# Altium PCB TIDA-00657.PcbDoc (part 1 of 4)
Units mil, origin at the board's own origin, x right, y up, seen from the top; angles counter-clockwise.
Board outline 2500 x 2500 mil, 4 copper layers (Top Layer, MidLayer1, MidLayer2, Bottom Layer); 149 components, 57 nets, 332 pads, 124 vias.
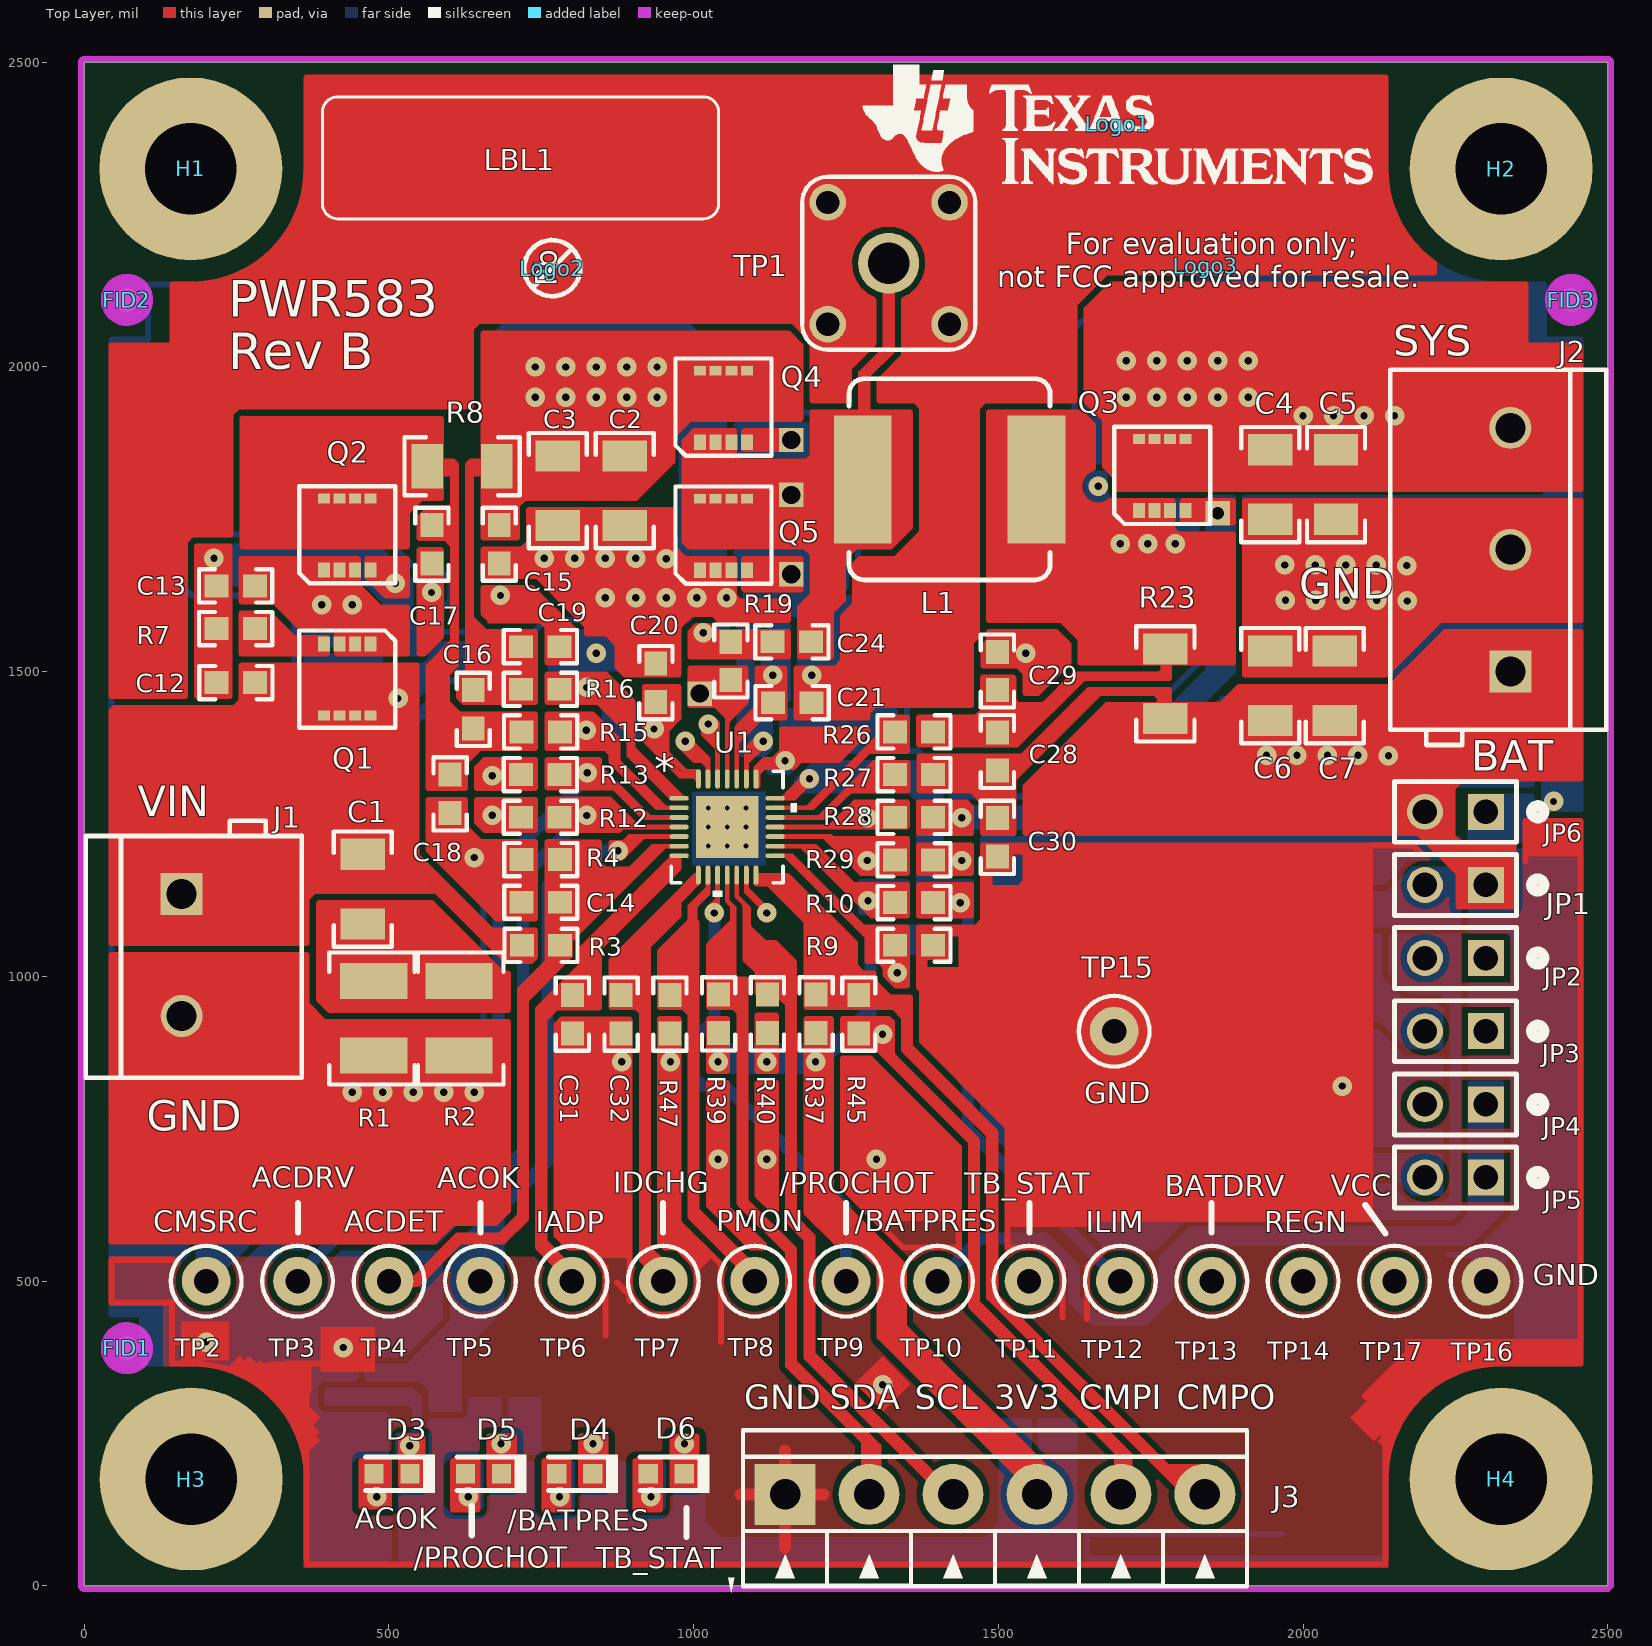
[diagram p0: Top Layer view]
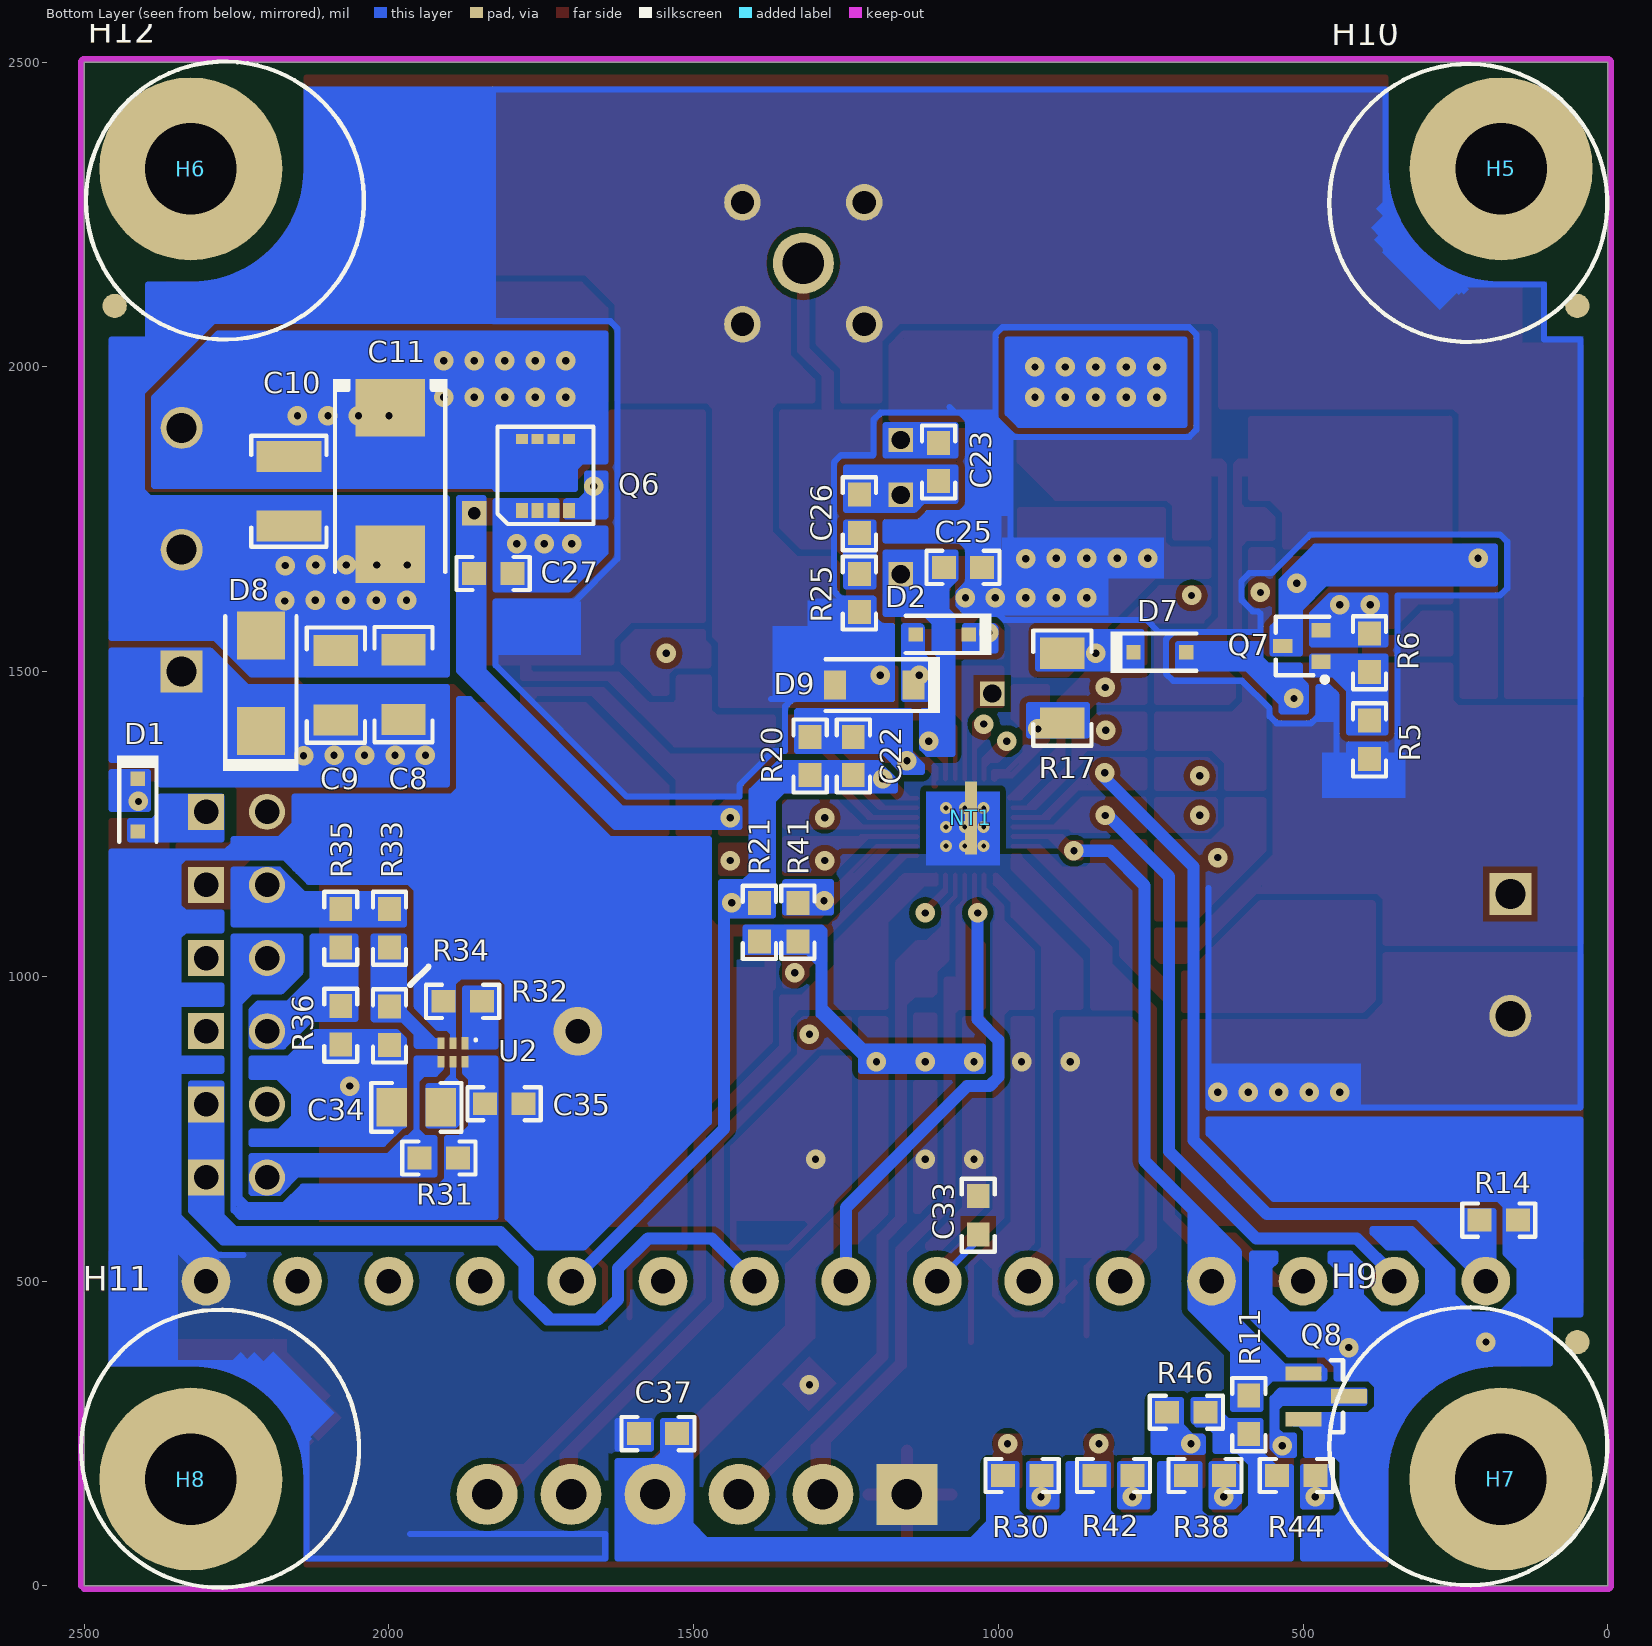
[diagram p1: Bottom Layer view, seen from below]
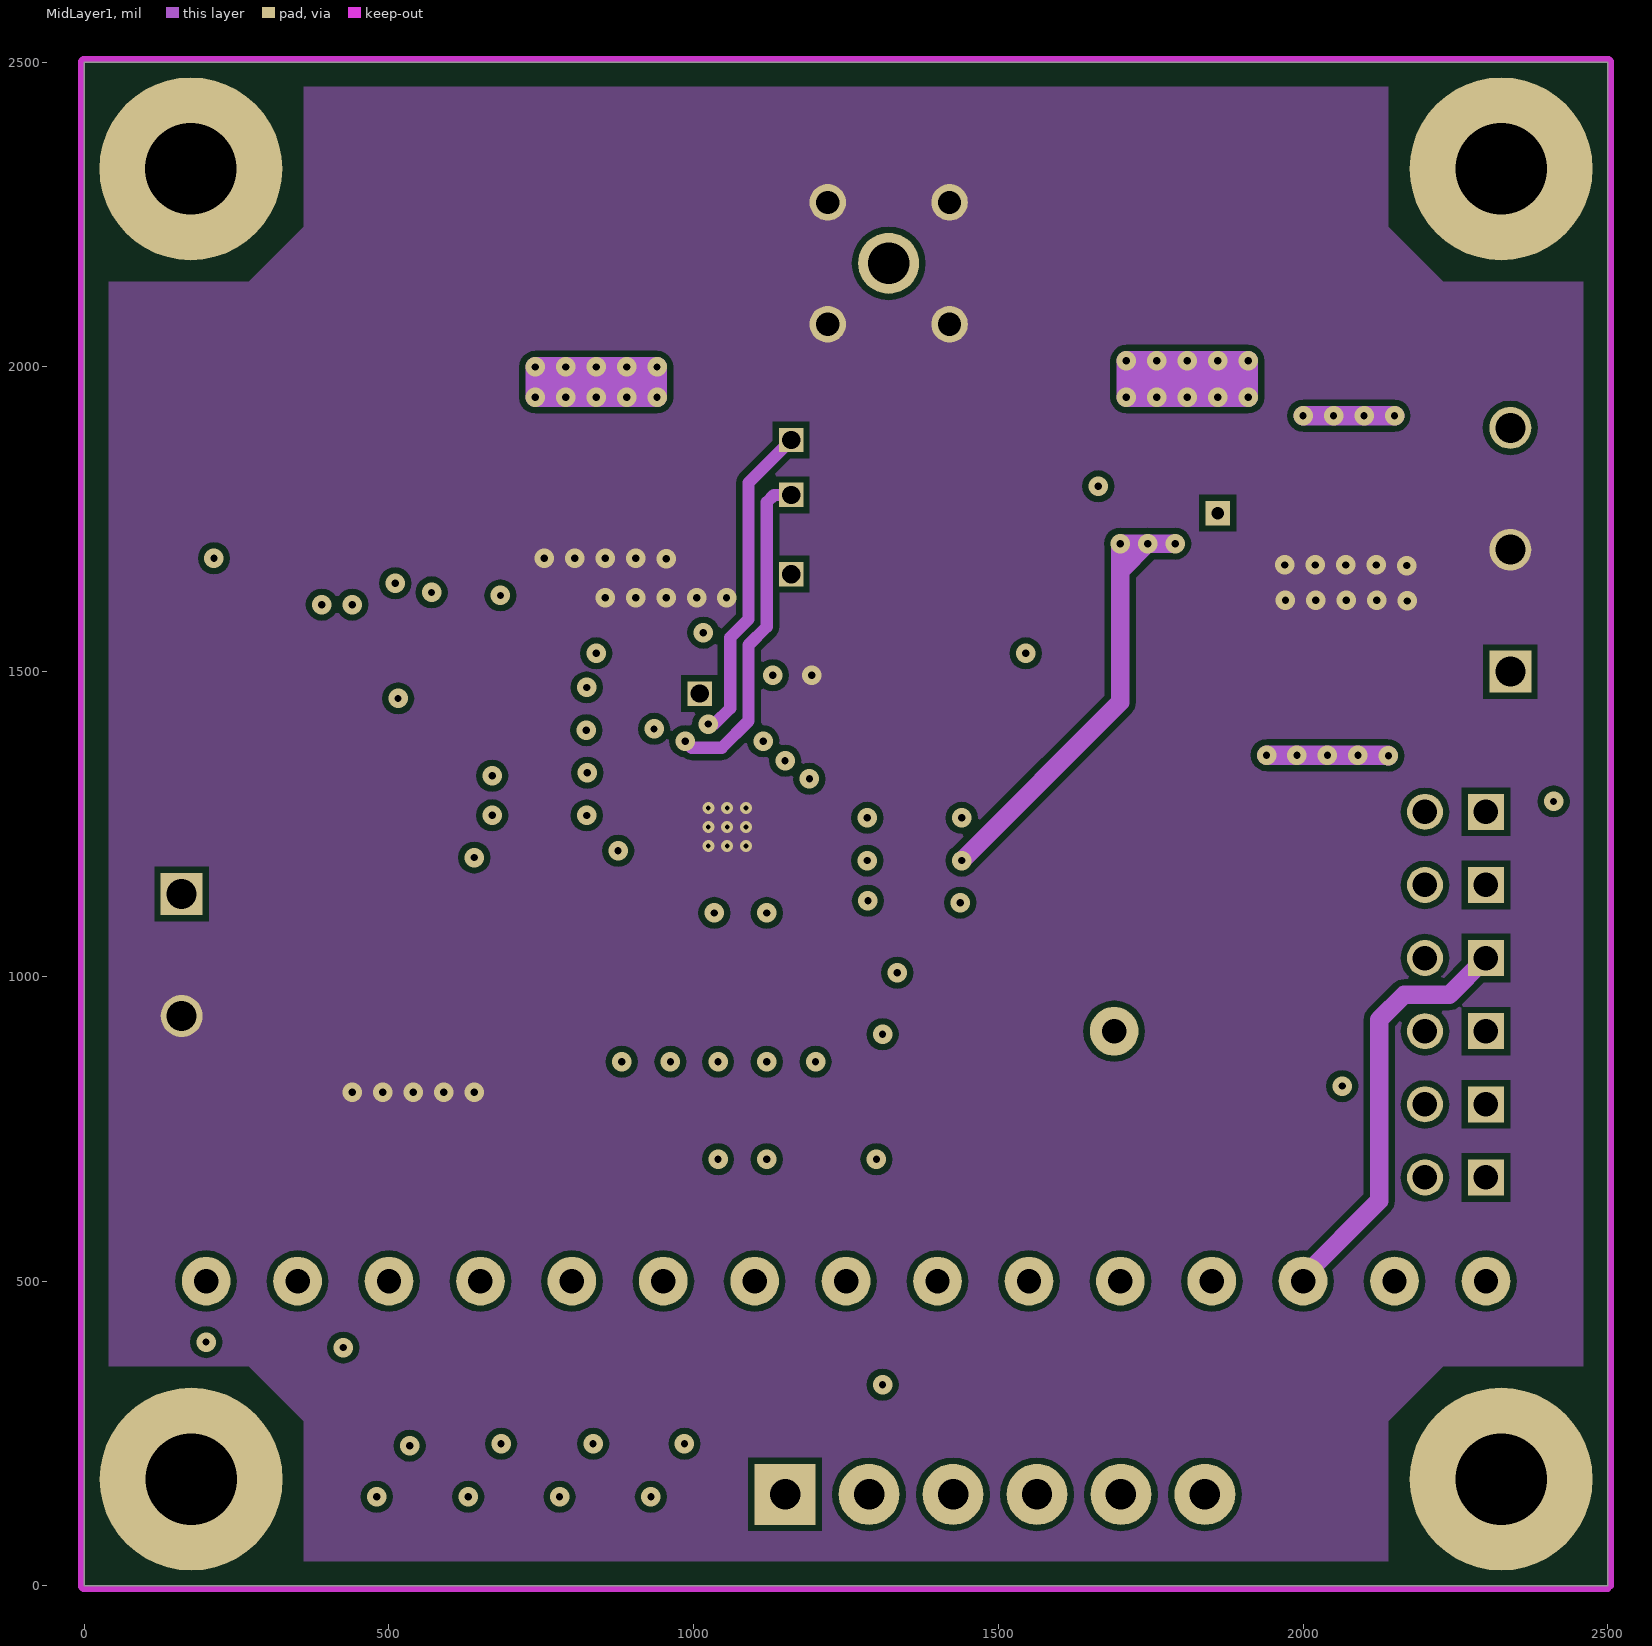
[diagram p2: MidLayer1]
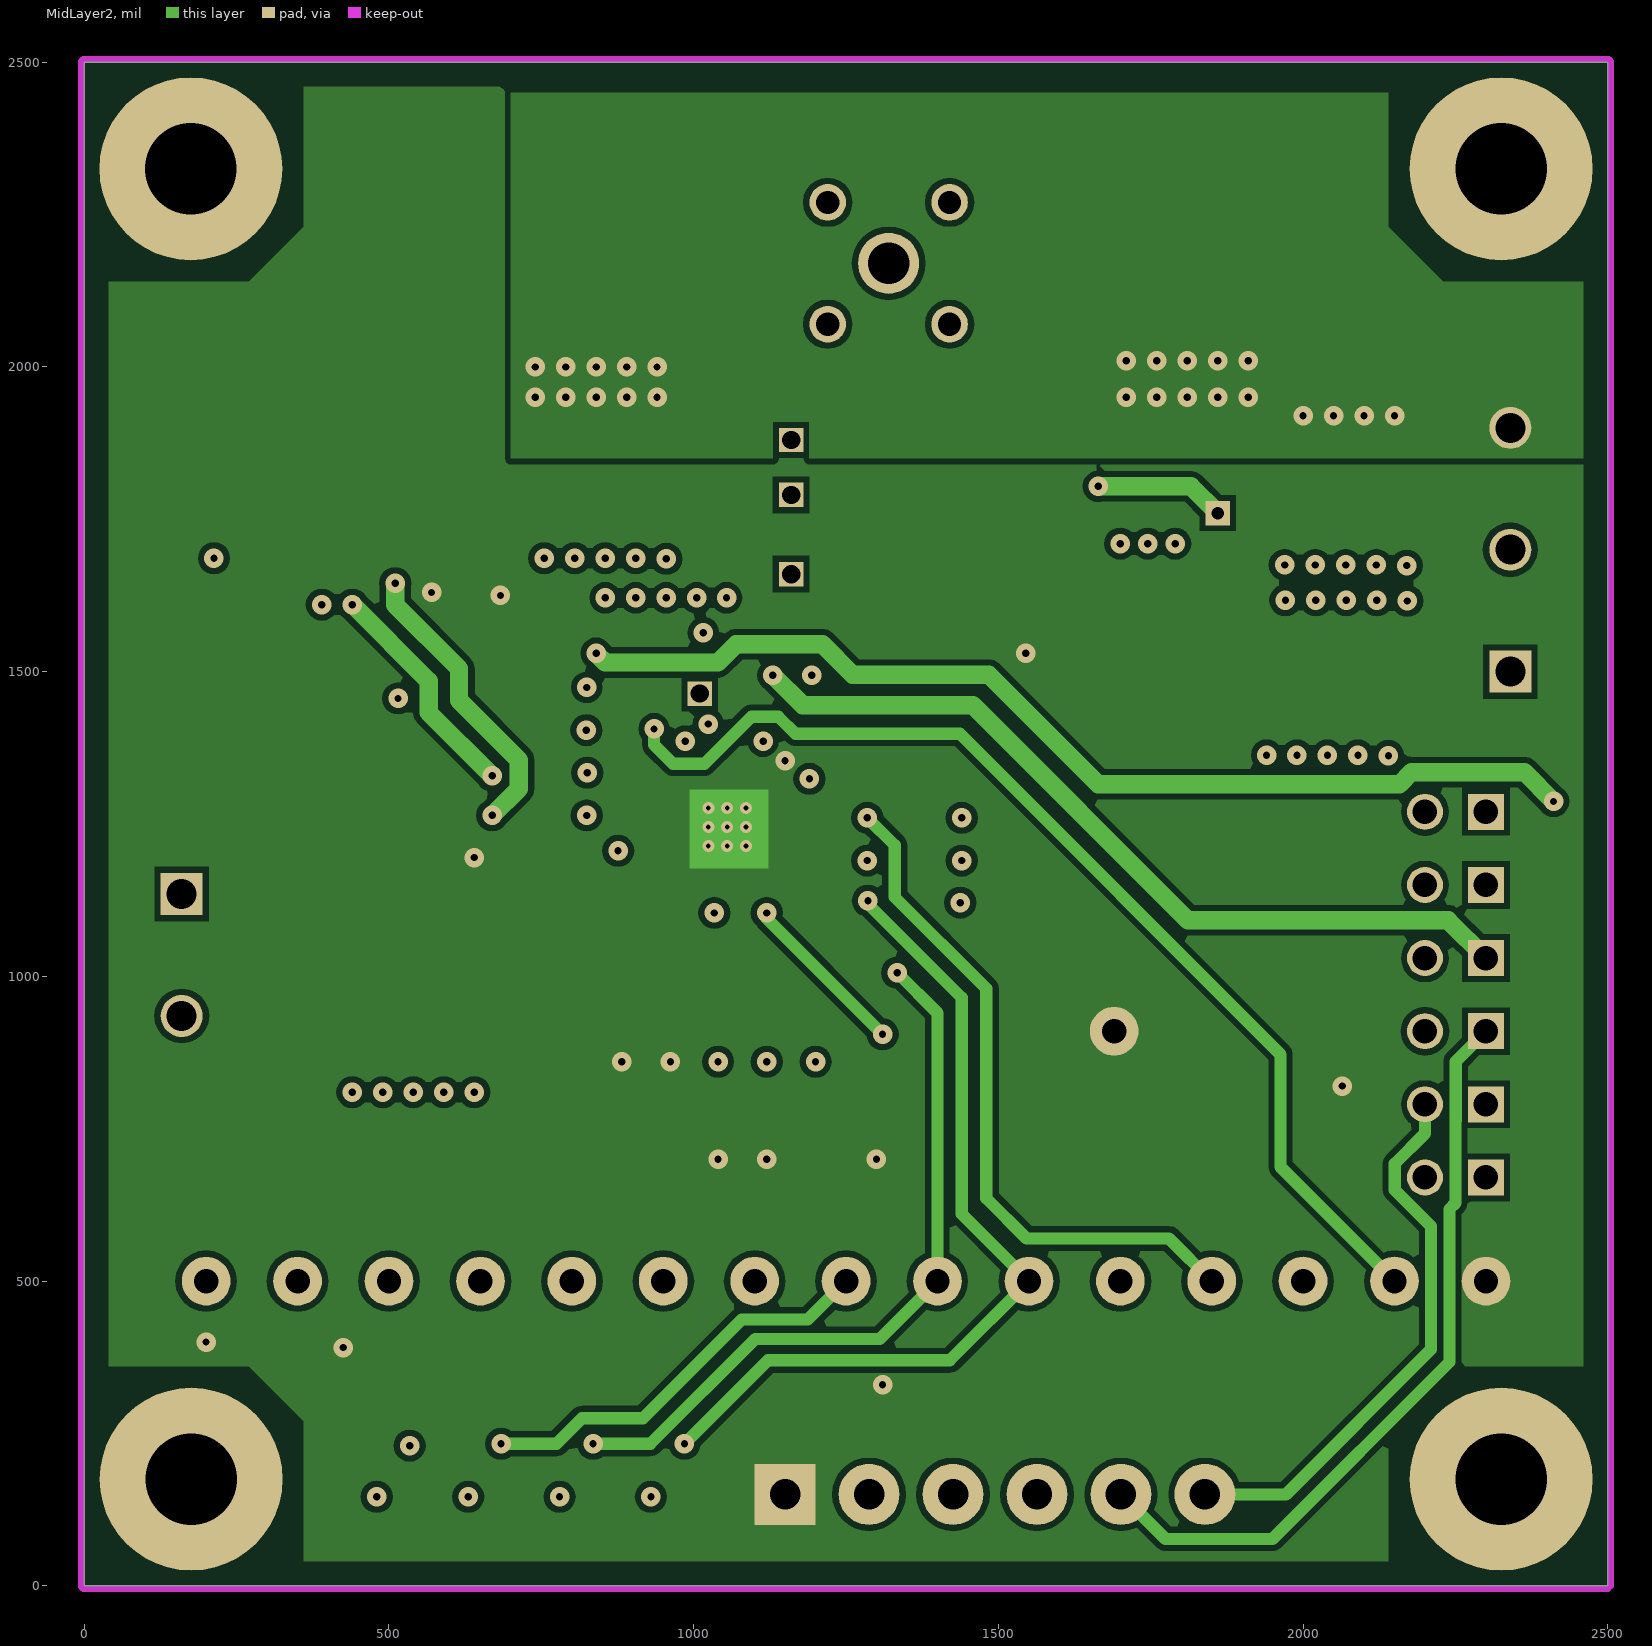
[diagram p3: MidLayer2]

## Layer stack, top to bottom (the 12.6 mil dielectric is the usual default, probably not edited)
Top Solder: solder mask 0.4, Solder Resist, Dk 3.5
Top Layer: signal copper 2.8
Dielectric1: core 12.6, FR-4, Dk 4.8
MidLayer1: signal copper 2.8
Dielectric2: prepreg 12.6, FR-4, Dk 4.8
MidLayer2: signal copper 2.8
Dielectric3: core 12.6, FR-4, Dk 4.8
Bottom Layer: signal copper 2.8
Bottom Solder: solder mask 0.4, Solder Resist, Dk 3.5

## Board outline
0,0 2500,0 2500,2500 0,2500 0,0

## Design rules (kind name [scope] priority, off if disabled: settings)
AcuteAngle [All] p1 off: minimum=4.50000000000000E+0001 checktracksonly=FALSE
AssemblyTestPointUsage [All] p1: valid=2
Clearance Clearance_BoardEdge_MountingHoles [OnCopper and InComponentClass('Mounting Holes') vs IsKeepOut] p1: gap=20
Clearance Clearance_BoardEdge_Poly [OnCopper and InPoly vs IsKeepOut] p2: gap=10
Clearance Clearance_BoardEdge [OnCopper and Not InComponentClass('Logo') and not InComponentClass('FiducialMark') and not InRegion(1000,500,4000,800) and Not IsKeepout vs IsKeepOut] p3: gap=20
Clearance Clearance_Poly [InPolygon] p4: gap=10
Clearance [All] p5: gap=6
ComponentClearance ComponentClearance_Logo [InComponentClass(Logo)] p1: gap=0 collisioncheckmode=3 verticalgap=0 showdistances=FALSE
ComponentClearance ComponentClearance_ScrewToNut [(HasFootprint('NY PMS 440 0025 PH')) vs (HasFootprint('Keystone_1902C'))] p2: gap=0 collisioncheckmode=3 verticalgap=0 showdistances=FALSE
ComponentClearance ComponentClearance_MountingHoles [InComponentClass('Mounting Holes')] p3: gap=0 collisioncheckmode=3 verticalgap=100000 showdistances=FALSE
ComponentClearance ComponentClearance_SmallPassives [HasFootprint('0201*') or HasFootprint('0402*') or HasFootprint('0508') or HasFootprint('0603*') or HasFootprint('0612') or HasFootprint('0805*') or HasFootprint('0815*') or HasFootprint('0830*') or HasFootprint('1206*') or HasFootprint('1210*') or HasFootprint('1808*') or HasFootprint('1812*') or HasFootprint('1825*') or HasFootprint('2010*') or HasFootprint('2220*') or HasFootprint('2225*') or HasFootprint('2512*') or HasFootprint('2728*') or HasFootprint('3518*') vs HasFootprint('0201*') or HasFootprint('0402*') or HasFootprint('0508') or HasFootprint('0603*') or HasFootprint('0612') or HasFootprint('0805*') or HasFootprint('0815*') or HasFootprint('0830*') or HasFootprint('1206*') or HasFootprint('1210*') or HasFootprint('1808*') or HasFootprint('1812*') or HasFootprint('1825*') or HasFootprint('2010*') or HasFootprint('2220*') or HasFootprint('2225*') or HasFootprint('2512*') or HasFootprint('2728*') or HasFootprint('3518*')] p4: gap=0 collisioncheckmode=3 verticalgap=0 showdistances=FALSE
ComponentClearance ComponentClearance_THtoSMT [IsThruComponent vs IsSMTComponent] p5: gap=0 collisioncheckmode=3 verticalgap=0 showdistances=FALSE
ComponentClearance ComponentClearance_THtoTH [IsThruComponent vs IsThruComponent] p6: gap=0 collisioncheckmode=3 verticalgap=0 showdistances=FALSE
ComponentClearance [All] p7: gap=0 collisioncheckmode=3 verticalgap=0 showdistances=FALSE
DiffPairsRouting [All] p1: maxlimit=100 minlimit=10 mostfreqgap=10 toplayer_minwidth=15 toplayer_maxwidth=15 toplayer_prefwidth=15 midlayer1_minwidth=15 midlayer1_maxwidth=15 midlayer1_prefwidth=15 midlayer2_minwidth=15 midlayer2_maxwidth=15 midlayer2_prefwidth=15 bottomlayer_minwidth=15 bottomlayer_maxwidth=15 bottomlayer_prefwidth=15 maxuncoupledlength=1000
FabricationTestPointUsage TestPointUsage [All] p1: valid=2 allowmultiple=FALSE
FabricationTestpoint Testpoint [All] p1: side=3 testpointundercomponent=TRUE minsize=40 maxsize=100 preferedsize=60 minholesize=0 maxholesize=40 preferedholesize=32 testpointgrid=1 allowsidetop=TRUE allowsidebottom=TRUE usegrid=TRUE gridtolerance=0.01
FanoutControl Fanout_LCC [IsLCC] p1: bgadir=Out bgaviamode=Centered fanoutstyle=Auto fanoutdirection=Alternating viagrid=1 // Fanout_LCC (Default Rule)
FanoutControl Fanout_BGA [IsBGA] p2: bgadir=Out bgaviamode=Centered fanoutstyle=Auto fanoutdirection=Alternating viagrid=1 // Fanout_BGA (Default Rule)
FanoutControl Fanout_Default [All] p4: bgadir=Out bgaviamode=Centered fanoutstyle=Auto fanoutdirection=Alternating viagrid=1 // Fanout_Default (Default Rule)
FanoutControl Fanout_Small [(CompPinCount < 5)] p5: bgadir=Out bgaviamode=Centered fanoutstyle=Auto fanoutdirection=OutThenIn viagrid=1 // Fanout_Small (Default Rule)
HoleSize [All] p1: absolutevalues=TRUE maxlimit=251 minlimit=6 maxpercent=80.000 minpercent=20.000
MinimumAnnularRing [All] p1: minimumring=5
MinimumSolderMaskSliver MinimumSolderMaskSliver_Logo [InComponentClass('Logo') vs InComponentClass('Logo')] p1: minsoldermaskwidth=0.7
MinimumSolderMaskSliver [All] p2: minsoldermaskwidth=4
PlaneClearance [All] p1: clearance=10
PlaneConnect [All] p1: planeconnectstyle=Direct reliefexpansion=10 reliefentries=4 reliefconductorwidth=10 reliefairgap=10
PolygonConnect [All] p1: connectstyle=Direct reliefconductorwidth=10 reliefentries=4 polygonreliefangle="90 Angle" airgapwidth=10
RoutingVias [All] p1: holewidth=16 width=34 viastyle="Through Hole" minholewidth=5 minwidth=18 maxholewidth=200 maxwidth=400
SMDToCorner [All] p1: distance=0
ShortCircuit [All] p1: allowed=TRUE
SilkToBoardRegionClearance [All] p1 off:
SilkToSilkClearance [All] p1: silktosilkclearance=0
SilkToSolderMaskClearance SilkscreenOverComponentPads [IsPad] p1: minsilkscreentomaskgap=0 clearancetoexposedcopper=TRUE
SolderMaskExpansion [All] p1: expansion=0
UnpouredPolygon [All] p1: allowunpoured=FALSE
Width [All] p1: maxlimit=100 minlimit=6 preferedwidth=10 checkconnectedcopper=TRUE
12 further rules are at their usual default settings.

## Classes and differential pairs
component class AssemblyNote: ZZ1 ZZ2 ZZ3 ZZ4
component class Label: LBL1
component class FiducialMark: FID1 FID2 FID3
component class "PWR583RevB Hardware_ANSI-B": FID1 FID2 FID3 H1 H2 H3 H4 H5 H6 H7 H8 H9 H10 H11 H12 LBL1 Logo1 Logo2 Logo3 ZZ1 ZZ2 ZZ3 ZZ4
component class Logo: Logo1
component class "Mounting Holes": H1 H2 H3 H4
component class PWR583RevB: C1 C2 C3 C4 C5 C6 C7 C8 C9 C10 C11 C12 C13 C14 C15 C16 C17 C18 C19 C20 C21 C22 C23 C24 C25 C26 C27 C28 C29 C30 C31 C32 C33 C34 C35 C37 D1 D2 D3 D4 D5 D6 D7 D8 D9 J1 J2 J3 JP1 JP2 JP3 JP4 JP5 JP6 L1 NT1 Q1 Q2 Q3 Q4 Q5 Q6 Q7 Q8 R1 R2 R3 R4 R5 R6 R7 R8 R9 R10 R11 R12 R13 R14 R15 R16 R17 R19 R20 R21 R23 R25 R26 R27 R28 R29 R30 R31 R32 R33 R34 R35 R36 R37 R38 R39 R40 R41 R42 R44 R45 R46 R47 TP1 TP2 TP3 TP4 TP5 TP6 TP7 TP8 TP9 TP10 TP11 TP12 TP13 TP14 TP15 TP16 TP17 U1 U2

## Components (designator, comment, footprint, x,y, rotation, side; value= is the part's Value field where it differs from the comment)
C1 "GRM31MR71E225KA93L" 1206 457,1143.24 r270 top
C2 "GRM31CR61E106KA12L" 1206 887,1796.91 r270 top
C3 "GRM31CR61E106KA12L" 1206 777,1796.91 r270 top
C4 "GRM31CR61E106KA12L" 1206 1946,1807 r270 top
C5 "GRM31CR61E106KA12L" 1206 2054,1807 r270 top
C6 "GRM31CR61E106KA12L" 1206 1946,1477 r90 top
C7 "GRM31CR61E106KA12L" 1206 2052,1477 r90 top
C8 "GRM31CR61E106KA12L" 1206 1976,1478.76 r90 bottom
C9 "GRM31CR61E106KA12L" 1206 2087,1477.76 r90 bottom
C10 "GRM32ER61E226KE15L" 1210 2164,1795.98 r270 bottom
C11 "16TQC150MYF" 7343-28 1998,1812.98 r270 bottom
C12 "GRM188R71H102KA01D" 0603 249,1482 r180 top
C13 "GRM188R71H473KA61D" 0603 248.54,1640.66 r180 top
C14 "GRM188R71E104KA01D" 0603 749.13,1121.63 r180 top
C15 "GRM188R71E105KA12D" 0603 681,1709 r270 top
C16 "GRM188R71E104KA01D" 0603 638.37,1438.13 r90 top
C17 "GRM188R71E105KA12D" 0603 570.54,1708.99 r270 top
C18 "GRM188R71E104KA01D" 0603 600.37,1299.45 r270 top
C19 "GRM188R71E104KA01D" 0603 748.5,1541 r0 top
C20 "GRM188R71E105KA12D" 0603 938,1482.06 r90 top
C21 "GRM188R61C225KE15D" 0603 1161.5,1449 r0 top
C22 "C0603X103K5RACTU" 0603 1238,1361.5 r270 bottom
C23 "GRM188R71E104KA01D" 0603 1098,1844 r270 bottom
C24 "GRM188R71H473KA61D" 0603 1161.14,1548.87 r0 top
C25 "GRM188R71H471KA01D" 0603 1058,1671 r180 bottom
C26 "GRM188R71E104KA01D" 0603 1228,1759 r270 bottom
C27 "C0603X103K5RACTU" 0603 1829,1661 r180 bottom
C28 "GRM188R71E104KA01D" 0603 1498.5,1369 r270 top
C29 "GRM188R71E104KA01D" 0603 1498.5,1501 r90 top
C30 "GRM188R71E104KA01D" 0603 1498.5,1228 r270 top
C31 "C0603C101J5GAC" 0603 801,938 r270 top
C32 "C0603C101J5GAC" 0603 881,938 r270 top
C33 "C0603C101J5GAC" 0603 1033,608 r90 bottom
C34 "C2012C0G1H222J" 0805_HV 1955,785 r180 bottom
C35 "GRM188R71E104KA01D" 0603 1811,791 r0 bottom
C37 "GRM188R71A225KE15D" 0603 1558.48,249.77 r0 bottom
D1 "BAT54HT1G" sod-323 2412,1281 r270 bottom
D2 "BAT54HT1G" sod-323 1092,1561 r0 bottom
D3 "LTST-C190GKT" LED_LTST-C190 505.06,184 r0 top
D4 "LTST-C190GKT" LED_LTST-C190 805,184 r0 top
D5 "LTST-C190KFKT" LED_LTST-C190 655,184 r0 top
D6 "LTST-C190KFKT" LED_LTST-C190 955,184 r0 top
D7 "BAT54HT1G" sod-323 735,1532 r180 bottom
D8 "SS12-E3/61T" SMA 2210,1480.95 r90 bottom
D9 "BZT52C8V2-7-F" SOD-123 1203.5,1478 r0 bottom
FID1 "Fiducial" Fiducial10-20 70,390 r0 top
FID2 "Fiducial" Fiducial10-20 70,2110 r0 top
FID3 "Fiducial" Fiducial10-20 2440,2110 r0 top
H1 "NY PMS 440 0025 PH" "NY PMS 440 0025 PH" 175,2325 r0 top locked
H2 "NY PMS 440 0025 PH" "NY PMS 440 0025 PH" 2325,2325 r0 top locked
H3 "NY PMS 440 0025 PH" "NY PMS 440 0025 PH" 175.53,175 r0 top locked
H4 "NY PMS 440 0025 PH" "NY PMS 440 0025 PH" 2325,175 r0 top locked
H5 "1902C" Keystone_1902C 175,2325 r180 bottom locked
H6 "1902C" Keystone_1902C 2325.53,2325 r180 bottom locked
H7 "1902C" Keystone_1902C 175.53,175 r180 bottom locked
H8 "1902C" Keystone_1902C 2325,175 r180 bottom locked
H9 "SJ-5303 (CLEAR)" Bumpon_SJ5003Transparent 229,229 r90 bottom
H10 "SJ-5303 (CLEAR)" Bumpon_SJ5003Transparent 229,2269 r90 bottom
H11 "SJ-5303 (CLEAR)" Bumpon_SJ5003Transparent 2277,225 r90 bottom
H12 "SJ-5303 (CLEAR)" Bumpon_SJ5003Transparent 2269,2273 r90 bottom
J1 "ED120/2DS" CONN_ED120-2DS 160,1035 r180 top locked
J2 "ED120/3DS" CONN_ED120_3DS 2340,1700 r180 top locked
J3 "ED555/6DS" TERM_BLK_ED555-6DS 1150,150 r0 top
JP1 "5-146261-1" CONN_5-146261-1 2250,1150 r180 top
JP2 "5-146261-1" CONN_5-146261-1 2250,1030 r180 top
JP3 "5-146261-1" CONN_5-146261-1 2250,910 r180 top
JP4 "5-146261-1" CONN_5-146261-1 2250,790 r180 top
JP5 "5-146261-1" CONN_5-146261-1 2250,670 r180 top
JP6 "5-146261-1" CONN_5-146261-1 2250,1270 r180 top
L1 "IHLP3232DZER3R3M01" IHLP-3232DZ 1419.94,1815.59 r0 top
LBL1 "Size: 0.65\" x 0.20 \"" Label_650x200 716,2343 r0 top
Logo1 "Texas Instruments" TI_Stacked_Overlay_Small 1696,2398 r0 top
Logo2 "Pb-Free Symbol" Pb-Free_Overlay_Small 768,2162 r90 top
Logo3 "FCC disclaimer" FCC_disclaimer_stacked 1840,2166 r0 top
NT1 "Net-Tie" Net-Tie_20milWide_60milLong 1045,1260 r90 bottom net-tie
Q1 "CSD17308Q3" TRANS_NEXFET_Q3 431.61,1486.66 r270 top locked
Q2 "CSD17308Q3" TRANS_NEXFET_Q3 431.54,1725.66 r90 top locked
Q3 "CSD17308Q3" TRANS_NEXFET_Q3 1769,1823 r90 top
Q4 "CSD17308Q3" TRANS_NEXFET_Q3 1049,1935 r90 top locked
Q5 "CSD17308Q3" TRANS_NEXFET_Q3 1049,1725 r90 top locked
Q6 "DNP" TRANS_NEXFET_Q3 1743,1823 r90 bottom
Q7 "BSS138W-7-F" SOT-323 502,1542 r0 bottom
Q8 "2N7002ET1G" SOT-23 462,311 r180 bottom
R1 "ERJ-14YJ3R9U" 1210M 475,931 r90 top
R2 "ERJ-14YJ3R9U" 1210M 615,931 r90 top
R3 "RC0603FR-07430KL" 0603 749.5,1051 r180 top
R4 "CRCW060366K5FKEA" 0603 749.13,1191.63 r0 top
R5 "CRCW06031M00FKEA" 0603 391,1388 r90 bottom
R6 "CRCW06033M01FKEA" 0603 391,1531 r90 bottom
R7 "CRCW06034R70JNEA" 0603 248.54,1570.66 r0 top
R8 "WSLP1206R0100FEA" 1206 620,1837 r0 top
R9 "CRCW060310K0FKEA" 0603 1361.5,1051 r0 top
R10 "RG1608P-8452-B-T5" 0603 1361.5,1121 r180 top
R11 "CRCW060310K0FKEA" 0603 589,281 r270 bottom
R12 "CRCW06034K02FKEA" 0603 748.5,1261.06 r180 top
R13 "CRCW06034K02FKEA" 0603 748.5,1331.06 r180 top
R14 "CRCW06030000Z0EA" 0603 179,600 r180 bottom
R15 "CRCW06030000Z0EA" 0603 748.85,1401.06 r180 top
R16 "CRCW06030000Z0EA" 0603 748.5,1471.06 r180 top
R17 "ERJ-8ENF10R0V" 1206 895,1473 r90 bottom
R19 "CRCW06036R80JNEA" 0603 1061,1517.5 r90 top
R20 "CRCW0603100KJNEA" 0603 1309,1361.5 r90 bottom
R21 "CRCW0603316KFKEA" 0603 1392,1088.5 r90 bottom
R23 "WSLP1206R0100FEA" 1206 1774,1480 r270 top
R25 "CRCW0603100KFKEA" 0603 1228,1629 r90 bottom
R26 "RC0603FR-0710RL" 0603 1361.5,1401 r0 top
R27 "RC0603FR-0710RL" 0603 1361.5,1331 r0 top
R28 "CRCW06034K02FKEA" 0603 1361.5,1261 r180 top
R29 "RC0603FR-0710RL" 0603 1361.5,1191 r0 top
R30 "CRCW06032K00FKEA" 0603 961,181 r180 bottom
R31 "CRCW060310K0FKEA" 0603 1918,702 r0 bottom
R32 "CRCW060310K0FKEA" 0603 1879,959 r0 bottom
R33 "CRCW0603499KFKEA" 0603 1999,1079 r90 bottom
R34 "CRCW060349K9FKEA" 0603 1999,918.7 r90 bottom
R35 "CRCW0603140KFKEA" 0603 2079,1079 r90 bottom
R36 "CRCW0603100KJNEA" 0603 2079,919.7 r90 bottom
R37 "CRCW060310K0FKEA" 0603 1201,938.5 r270 top
R38 "CRCW06032K00FKEA" 0603 661,181 r180 bottom
R39 "CRCW060310K0FKEA" 0603 1041,938.5 r270 top
R40 "CRCW060310K0FKEA" 0603 1121,938.5 r90 top
R41 "CRCW060310K0FKEA" 0603 1329,1089 r270 bottom
R42 "CRCW06032K00FKEA" 0603 811,181 r180 bottom
R44 "CRCW06032K00FKEA" 0603 511,181 r180 bottom
R45 "CRCW06031M00FKEA" 0603 1271,938 r90 top
R46 "CRCW060310K0FKEA" 0603 691.52,284.77 r180 bottom
R47 "CRCW060330K1FKEA" 0603 961,938 r270 top
TP1 "131-5031-00" Tek_131-5031-00 1320,2170 r0 top locked
TP2 "5002" Keystone5002 200.18,499.88 r0 top
TP3 "5002" Keystone5002 350.18,499.88 r0 top
TP4 "5002" Keystone5002 500.18,499.88 r0 top
TP5 "5002" Keystone5002 650.18,499.88 r0 top
TP6 "5002" Keystone5002 800.18,499.88 r0 top
TP7 "5002" Keystone5002 950.18,499.88 r0 top
TP8 "5002" Keystone5002 1100.18,499.88 r0 top
TP9 "5002" Keystone5002 1250.18,499.88 r0 top
TP10 "5002" Keystone5002 1400.18,499.88 r0 top
TP11 "5002" Keystone5002 1550.18,499.88 r0 top
TP12 "5002" Keystone5002 1700.18,499.88 r0 top
TP13 "5002" Keystone5002 1850.18,499.88 r0 top
TP14 "5003" Keystone5003 2000,500 r0 top
TP15 "5001" Keystone5001 1690,910 r0 top
TP16 "5001" Keystone5001 2300.18,499.88 r0 top
TP17 "5002" Keystone5002 2150,500 r90 top
U1 "BQ24780SRUY" RUY0028A 1055,1245.06 r0 top locked
U2 "TPS3898ADRY" DRY0006A 1895,875 r270 bottom
ZZ1 "This Assembly Note is for PCB labels only" AssemblyNoteLabel 2349,4761 r0 top
ZZ2 "These assemblies are ESD sensitive, ESD precautions shall be observed." AssemblyNote 2354,4644 r0 top
ZZ3 "These assemblies must be clean and free from flux and all contaminants. Use of no clean flux is not acceptable." AssemblyNote 2354,4523 r0 top
ZZ4 "These assemblies must comply with workmanship standards IPC-A-610 Class 2, unless otherwise specified." AssemblyNote 2354,4392 r0 top

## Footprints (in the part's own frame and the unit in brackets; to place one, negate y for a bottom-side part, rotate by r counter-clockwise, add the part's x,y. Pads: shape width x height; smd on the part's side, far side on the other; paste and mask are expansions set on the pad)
0603 [mm] "0603 from SM-752 data"
  rect 1x0.95 smd: 1(-0.8,0) 2(0.8,0)
  silkscreen extent -1.52,-0.69 1.52,0.69, body extent -0.87,-0.47 0.87,0.47, height 0.85
0805_HV [mil] "0805 with 30mil clearance between pads"
  rect 50x63 smd: 1(-40,0) 2(40,0)
  silkscreen extent -74,-40 74,40, body extent -43,-29 43,29, height 43
1206 [mm] "1206 from SM-752 data"
  rect 1.3x1.85 smd: 1(-1.45,0) 2(1.45,0)
  silkscreen extent -2.4,-1.21 2.4,1.21, body extent -1.7,-0.9 1.7,0.9, height 1.35
1210 [mm] "1210 from SM-752 data"
  rect 1.3x2.7 smd: 1(-1.45,0) 2(1.45,0)
  silkscreen extent -2.32,-1.57 2.32,1.57, body extent -1.7,-1.35 1.7,1.35, height 1.35
1210M [mm] "1210 from SM-752 data"
  rect 1.5x2.8 smd: 1(-1.55,0) 2(1.55,0)
  silkscreen extent -2.75,-1.85 2.75,1.85, body extent -1.7,-1.35 1.7,1.35, height 1.35
7343-28 [mm] "Panasonic recommended land pattern for size code D3L"
  rect 2.4x2.9 smd: 1(-3.05,0) 2(3.05,0)
  silkscreen extent -4.25,-2.39 3.8,2.39, body extent -3.8,-2.3 3.8,2.3, height 2.9
AssemblyNote [mil] "Assembly Note"
AssemblyNoteLabel [mil] "Assembly Note for PCB Labels"
Bumpon_SJ5003Transparent [mil] "3M Hemispherical Bumpon transparent"
  round 1 on Mech4: 0(0,0)
  silkscreen extent -228,-228 228,228, body extent -217,-218 219,218, height 197
CONN_5-146261-1 [mm] "Sullins"
  rect 1.5x1.5 hole 1.02: 1(-1.27,0)
  round 1.5 hole 1.02: 2(1.27,0)
  silkscreen extent -3.68,-1.27 2.54,1.27, body extent -2.51,-1.27 2.51,1.27, height 10.87
CONN_ED120-2DS [mm] "ONSHORE"
  rect 1.75x1.75 hole 1.25: 1(0,-2.54)
  round 1.75 hole 1.25: 2(0,2.54)
  silkscreen extent -5,-5.6 4,5.12, body extent -5,-5.6 4.15,5.12, height 13.1
CONN_ED120_3DS [mm] "ONSHORE"
  rect 1.75x1.75 hole 1.25: 1(0,5.08)
  round 1.75 hole 1.25: 2(0,0) 3(0,-5.08)
  silkscreen extent -4,-7.5 5,8.14, body extent -4.13,-7.55 5.05,8.14, height 13.1
DRY0006A [mm] "PSON, 6-Leads, Body 1x1.45mm, Pitch 0.5mm, TI Recommended"
  rect 0.52x0.3 smd paste+0: 1(-0.385,0.5)
  rect 0.49x0.3 smd paste+0: 2(-0.385,0) 3(-0.385,-0.5) 4(0.385,-0.5) 5(0.385,0) 6(0.385,0.5)
  silkscreen extent -0.57,0.9 -0.48,1, body extent -0.53,-0.75 0.53,0.75, height 0.61
FCC_disclaimer_stacked [mil]
Fiducial10-20 [mm]
  round 1 smd paste-0.5 mask+0.5: 1(0,0)
  Top Layer keep-out circle w1.178: c0,0 r0.5
IHLP-3232DZ [mil] "VISHAY"
  rect 95x210 smd: 1(-142.5,0) 2(142.5,0)
  silkscreen extent -165,-165 165,165, body extent -162,-162 162,162, height 158
Keystone5001 [mil] "For Keystone 500x miniature loop terminals"
  round 80 hole 40: 1(0,0)
  silkscreen extent -58,-58 58,58, body extent -49,-49 49,49, height 182
Keystone5002 [mil] "For Keystone 500x miniature loop terminals"
  round 80 hole 40: 1(0,0)
  silkscreen extent -58,-58 58,58, body extent -49,-49 49,49, height 182
Keystone5003 [mil] "For Keystone 500x miniature loop terminals"
  round 80 hole 40: 1(0,0)
  silkscreen extent -58,-58 58,58, body extent -49,-49 49,49, height 182
Keystone_1902C [mil] "Hex Standoff, 4-40 threaded, nylon"
  body extent -145,-126 146,126, height 501
Label_650x200 [mil] "Thermal Transfer Label"
  silkscreen extent -325,-100 325,100, body extent -326,-101 326,101, height 1
LED_LTST-C190 [mm] "Lite-On"
  rect 0.8x0.8 smd: 1(-0.75,0) 2(0.75,0)
  silkscreen extent -1.1,-0.8 1.8,0.8, body extent -0.85,-0.45 0.85,0.45, height 0.9
Net-Tie_20milWide_60milLong [mil] "20mil net tie, no solder mask opening, no solder paste"
  rect 60x20 smd paste-10 mask-10: 1(-30,0) 2(30,0)
"NY PMS 440 0025 PH" [mil] "4-40 nylon screw and mounting hole"
  round 300 hole 150: 1(0,0)
  body extent -130,-130 130,130, height 106
Pb-Free_Overlay_Small [mil]
  silkscreen extent -46,-46 46,46
RUY0028A [mm] "0.40mm pitch"
  oval 0.8x0.2 smd: 1(-2,1.2) 2(-2,0.8) 3(-2,0.4) 4(-2,0) 5(-2,-0.4) 6(-2,-0.8) 7(-2,-1.2) 15(2,-1.2) 16(2,-0.8) 17(2,-0.4) 18(2,0) 19(2,0.4) 20(2,0.8) 21(2,1.2)
  oval 0.2x0.8 smd: 8(-1.2,-2) 9(-0.8,-2) 10(-0.4,-2) 11(0,-2) 12(0.4,-2) 13(0.8,-2) 14(1.2,-2) 22(1.2,2) 23(0.8,2) 24(0.4,2) 25(0,2) 26(-0.4,2) 27(-0.8,2) 28(-1.2,2)
  rect 2.6x2.6 smd paste-1.287 mask-1.287: 29(0,0)
  silkscreen extent -2.33,-2.91 2.91,2.33, body extent -2.07,-2.07 2.07,2.07, height 0.81
SMA [mm] "Molded Diode, 2-Leads, Body 4.3x2.6mm, IPC Medium Density, based on OnSemi component dimensions and land pattern"
  rect 2x2 smd: 1(-2,0) 2(2,0)
  silkscreen extent -3.66,-1.57 2.79,1.57, body extent -2.6,-1.3 2.6,1.3, height 2.42
SOD-123 [mm] "On Semi recommended land pattern"
  rect 0.915x1.22 smd: 1(-1.637,0) 2(1.637,0)
  silkscreen extent -2.74,-1.17 2.03,1.17, body extent -1.93,-0.9 1.93,0.9, height 1.35
sod-323 [mm] "NXP recommended land pattern"
  rect 0.6x0.6 smd paste-0.05: 1(-1.1,0) 2(1.1,0)
  silkscreen extent -2.06,-0.86 1.53,0.86, body extent -1.3,-0.67 1.3,0.68, height 1.1
SOT-23 [mm] "SOT23, 3-Leads, Body 2.9x1.3mm, Pitch 0.95mm, Lead Span 2.5mm, IPC Medium Density"
  rect 1.5x0.6 smd: 1(-0.95,0.95) 2(-0.95,-0.95) 3(0.95,0)
  silkscreen extent 0.2,-1.5 0.7,1.5, body extent -1.16,-1.45 1.21,1.45, height 1
SOT-323 [mm] "Zetex recommended land pattern.  March 2007"
  rect 0.8x0.6 smd: 1(-0.8,0.65) 2(-0.8,-0.65) 3(0.8,0)
  silkscreen extent -1.14,-1.22 1.09,1.49, body extent -1.13,-1.13 1.12,1.12, height 1.13
Tek_131-5031-00 [mil] "Tektronix cold nose probe"
  round 100 hole 68: 1(0,0)
  round 60 hole 38: 2(-100,100) 3(-100,-100) 4(100,-100) 5(100,100)
  silkscreen extent -142,-142 142,142, body extent -206,-206 206,206, height 351
TERM_BLK_ED555-6DS [mm]
  rect 2.54x2.54 hole 1.27: 1(0,0)
  round 2.54 hole 1.27: 2(3.5,0) 3(7,0) 4(10.5,0) 5(14,0) 6(17.5,0)
  silkscreen extent -2.36,-4.09 19.25,2.67, body extent -1.75,-3.8 19.25,2.7, height 8.2
TI_Stacked_Overlay_Small [mil]
  silkscreen extent -418,-98 418,98
TRANS_NEXFET_Q3 [mm] "TI recommended land pattern (nominal) M0143-01"
  rect 0.63x0.5 smd mask+0.076: 1(-1.49,0.975) 2(-1.49,0.325) 3(-1.49,-0.325) 4(-1.49,-0.975)
  rect 0.41x0.5 smd mask+0.076: 5(1.49,-0.975) 6(1.49,-0.325) 7(1.49,0.325) 8(1.49,0.975)
  Top Layer region: -0.615,-1.225 1.285,-1.225 1.285,1.225 -0.615,1.225
  silkscreen extent -2.05,-2 2,2, body extent -1.76,-1.7 1.66,1.7, height 1.11

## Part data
C1: "CAP, CERM, 2.2uF, 25V, +/-10%, X7R, 1206"
C2 C3 C4 C5 C6 C7 C8 C9: "CAP, CERM, 10uF, 25V, +/-10%, X5R, 1206"
C10: "CAP, CERM, 22uF, 25V, +/-10%, X5R, 1210"
C11: "CAP, TA, 150uF, 16V, +/-20%, 0.05 ohm, SMD"
C12: "CAP, CERM, 1000pF, 50V, +/-10%, X7R, 0603"
C13 C24: "CAP, CERM, 0.047uF, 50V, +/-10%, X7R, 0603"
C14 C16 C18 C19 C23 C26 C28 C29 C30 C35: "CAP, CERM, 0.1uF, 25V, +/-10%, X7R, 0603"
C15 C17 C20: "CAP, CERM, 1uF, 25V, +/-10%, X7R, 0603"
C21: "CAP, CERM, 2.2uF, 16V, +/-10%, X5R, 0603"
C22 C27: "CAP, CERM, 0.01uF, 50V, +/-10%, X7R, 0603"
C25: "CAP, CERM, 470pF, 50V, +/-10%, X7R, 0603"
C31 C32 C33: "CAP, CERM, 100pF, 50V, +/-5%, C0G/NP0, 0603"
C34: "CAP, CERM, 2200pF, 50V, +/-5%, C0G/NP0, 0805"
C37: "CAP, CERM, 2.2uF, 10V, +/-10%, X7R, 0603"
D1 D2 D7: "Diode, Schottky, 30V, 0.2A, SOD-323"
D3 D4: "LED, Green, SMD"
D5 D6: "LED, Orange, SMD"
D8: "Diode, Schottky, 20V, 1A, SMA"
D9: "Diode, Zener, 8.2V, 500mW, SOD-123"
FID1 FID2 FID3: "Fiducial mark.  There is nothing to buy or mount."
H1 H2 H3 H4: "Machine Screw, Round, #4-40 x 1/4, Nylon, Philips panhead"
H5 H6 H7 H8: "Standoff, Hex, 0.5\"L #4-40 Nylon"
H9 H10 H11 H12: "Bumpon, Hemisphere, 0.44 X 0.20, Clear"
J1: "TERMINAL BLOCK 5.08MM VERT 2POS"
J2: "TERMINAL BLOCK 5.08MM VERT 3POS"
J3: "Terminal Block, 6A, 3.5mm Pitch, 6-Pos, TH"
JP1 JP2 JP3 JP4 JP5 JP6: "Header, 100mil, 2x1, Gold plated, TH"
L1: "Inductor, Shielded, Powdered Iron, 3.3uH, 9.2A, 17.7 ohm, SMD"
LBL1: library part THT-14-423-10, "Thermal Transfer Printable Labels, 0.650\" W x 0.200\" H - 10,000 per roll"
Logo1: library part TI_Logo, "Texas Instrument Corporate Signature"
Logo2: library part Pb-Free
Logo3: library part FCC_disclaimer, "FCC_disclaimer"
NT1: "Single point connection between nets."
Q1 Q2 Q3 Q4 Q5: "MOSFET, N-CH, 30V, 47A, SON 3.3x3.3mm"
Q6: library part CSD17308Q3, "MOSFET, N-CH, 30V, 47A, SON 3.3x3.3mm"
Q7: "MOSFET, N-CH, 50V, 0.2A, SOT-323"
Q8: "MOSFET, N-CH, 60V, 0.26A, SOT-23"
R1 R2: "RES, 3.9 ohm, 5%, 0.5W, 1210"
R3: "RES, 430k ohm, 1%, 0.1W, 0603"
R4: "RES, 66.5k ohm, 1%, 0.1W, 0603"
R5 R45: "RES, 1.00Meg ohm, 1%, 0.1W, 0603"
R6: "RES, 3.01Meg ohm, 1%, 0.1W, 0603"
R7: "RES, 4.7 ohm, 5%, 0.1W, 0603"
R8 R23: "RES, 0.01 ohm, 1%, 1W, 1206"
R9 R11 R31 R32 R37 R39 R40 R41 R46: "RES, 10.0k ohm, 1%, 0.1W, 0603"
R10: "RES, 84.5k ohm, 0.1%, 0.1W, 0603"
R12 R13 R28: "RES, 4.02k ohm, 1%, 0.1W, 0603"
R14 R15 R16: "RES, 0 ohm, 5%, 0.1W, 0603"
R17: "RES, 10.0 ohm, 1%, 0.25W, 1206"
R19: "RES, 6.8 ohm, 5%, 0.1W, 0603"
R20 R36: "RES, 100k ohm, 5%, 0.1W, 0603"
R21: "RES, 316k ohm, 1%, 0.1W, 0603"
R25: "RES, 100k ohm, 1%, 0.1W, 0603"
R26 R27 R29: "RES, 10.0 ohm, 1%, 0.1W, 0603"
R30 R38 R42 R44: "RES, 2.00k ohm, 1%, 0.1W, 0603"
R33: "RES, 499k ohm, 1%, 0.1W, 0603"
R34: "RES, 49.9k ohm, 1%, 0.1W, 0603"
R35: "RES, 140k ohm, 1%, 0.1W, 0603"
R47: "RES, 30.1k ohm, 1%, 0.1W, 0603"
TP1: "Compact Probe Tip Circuit Board Test Points, TH, 25 per"
TP2 TP3 TP4 TP5 TP6 TP7 TP8 TP9 TP10 TP11 TP12 TP13 TP17: "Test Point, TH, Miniature, White"
TP14: "Test Point, Miniature, Orange, TH"
TP15 TP16: "Test Point, Miniature, Black, TH"
U1: library part BQ24780RUY, "1-4 Cell Turbo Boost Mode Battery Charge Controller with Power Monitoring and /PROCHOT for CPU Throttling, RUY0028A"
U2: "Single-Channel, Adjustable Supervisory Circuit in Ultra-Small Package, DRY0006A"
ZZ1: library part AssemblyNoteLabel
ZZ2 ZZ3 ZZ4: library part AssemblyNote

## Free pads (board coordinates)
  round 40 smd far side: 0(50,400) 1(50,2100) 2(2450,2100)
  rect 40x40 hole 30: 0(1010,1464) 0(1160,1880) 1(1160,1660) 2(1160,1790)
  rect 40x40 hole 20: 0(1860,1760)

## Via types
v1: diameter 32, hole 12, Top Layer to Bottom Layer, tented both sides, 115 vias
v2: diameter 19.68, hole 7.87, Top Layer to Bottom Layer, tented both sides, 9 vias

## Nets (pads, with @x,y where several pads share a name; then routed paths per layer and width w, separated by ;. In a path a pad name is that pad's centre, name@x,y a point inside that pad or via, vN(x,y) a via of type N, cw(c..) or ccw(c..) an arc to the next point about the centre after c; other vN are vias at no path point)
3V3: C37.1 J3.4 R11.2 R21.1 R30.1 R37.2 R38.1 R39.2 R40.1 R41.2 R42.1 R44.1 R46.2 | length 8223.1
  Top Layer w10: 1031,930 1031,917 R39.2@1041,907 ; R40.1@1105,914 1112,907 R40.1@1121,907 ; R37.2@1201,907 1201,930 ; 1299,563 1297,565 1232.28,565 1185,612.28 1185,645 ; J3.4@1563.39,150 1305,408.39 1305,476.75 1305.18,476.93 1305.18,522.67 1191.84,636 1185,636 1185,645 ; J3.4@1584,170.61 1584,187 1345,426 1345,526 1225,646 1225,930 1201,930 ; 1185,645 1185,930 1201,930 ; 1025,845 1055,845 1055,930 1025,930 1025,845 ; 1105,845 1105,935.31 1135,935.31 1135,845 1105,845
  Bottom Layer w10: 520,105 520,119 ; R11.2@589,249.5 570.5,249.5 570,249 ; 658.28,110 670,121.72 670,194 ; R46.2@660.02,284.77 660.02,281.02 644,265 644,259.28 ; R38.1@692.5,181 683,181 670,194 ; 746.72,110 735,121.72 735,200 670,200 670,194 ; 808.28,110 820,121.72 820,200 885,200 885,121.72 896.72,110 ; 903,110 910,103 ; 1016,75 1044,75 ; v1@1025,860 v1(1040,860) ; 1025,868 1026,869 ; 1048,75 1044,75 ; 1217,859 1295,937 1295,1021 1314,1040 1415,1040 1415,1080 1381,1080 ; 1225,876 1285,936 1285,1075 1290,1080 1381,1080 ; 1295,959 1221,885 1186,885 ; R21.1@1392,1057 1392,1080 1381,1080 ; C37.1@1526.99,249.77 1505,227.78 ; 1568,205 1563.39,205 ; 520,119 520,45 1625,45 1625,205 1563.39,205 ; 520,119 520,195 547.28,195 570,217.72 570,249 ; 570,249 570,270 615,270 ; 606.36,221.64 615,230.28 ; 606.36,221.64 585,200.28 585,130.72 605.72,110 958.28,110 970,121.72 970,200 1015,200 1015,104 1044,75 ; 606.36,221.64 643.64,221.64 644,222 644,253 ; 615,230.28 644,259.28 ; 615,230.28 615,270 ; 615,270 623.28,270 635,281.72 635,305 680,305 680,271 674,265 656,265 ; 644,253 644,259.28 ; 644,253 656,265 ; 644,259.28 649.72,265 656,265 ; 1044,75 1479,75 1505,101 1505,205 ; 1186,885 1025,885 1025,845 1225,845 1225,885 1186,885 ; 1505,205 1505,227.78 ; 1505,205 1562,205 ; 1505,227.78 1505,270 1550,270 1550,217 1562,205 ; 1562,205 1563.39,205
  other v1: 1120,860 1200,860
\BATPRES: D4.2 JP4.1 JP5.1 R9.1 TP10.1 U1.15 | length 4884.3
  Top Layer w7.87: 1282,1077 1161.18,1197.82 U1.15@1133.74,1197.82 ; 1282.82,1072 1277.82,1077 ; 1298,1051 1151.18,1197.82 U1.15@1133.74,1197.82 ; 1321,1077 1277.82,1077 ; U1.15@1133.74,1197.82 1157,1197.82 1277.82,1077
  Top Layer w10: 815,184 D4.2@834.53,184 ; 815,188 818,191 ; 1273.91,1080.91 1274.83,1079.99 1330.01,1079.99 ; 1288,1072 1285,1069 1285,1025 1350,1025 ; 1305,1025 1315,1015 1315,1002 1332,985 1350,985 1350,1025 ; R9.1@1330,1051 1330.01,1079.99 ; 1330.01,1079.99 1349.99,1079.99 1350,1025 ; 815,165 815,245 855,245 855,165 815,165
  MidLayer2 w20: v1(835,233) 929,233 1101,405 1305.29,405 TP10.1@1400.18,499.88 1400.18,939.82 v1(1334,1006)
  Bottom Layer w10: 1700,437 1705,432 1741,432 1782,473 1782,525 1820,563 2273,563 2325,615 2325,824 2275,824 JP4.1@2275,815 ; 1816.72,585 2252.28,585 2275,607.72 JP4.1@2275,815 ; JP4.1@2300,790 JP4.1@2275,815
  Bottom Layer w20: TP10.1@1400.18,499.88 1470.29,570 1575,570 1624,521 1624,470 1657,437 1700,437 1735,437 1772,474 1772,535.28 1816.72,580 1840,580
\PROCHOT: D5.2 R46.1 TP9.1 U1.10 | length 2101.5
  Top Layer w7.87: v1@1026,1113 1039.25,1126.25 ; v1@1039.25,1109.25 1039.25,1126.25 ; U1.10@1039.25,1166.32 1039.25,1126.25
  Top Layer w10: 667,191 665,189 ; D5.2@684.53,184 665,184 ; 665,184 665,189 ; 665,184 665,165 705,165 705,245 665,245 665,189
  MidLayer2 w20: v1(684,233) 775,233 817,275 917,275 1079,437 1187.29,437 TP9.1@1250.18,499.88
  Bottom Layer w10: R46.1@723.01,284.77 700.23,284.77 700,284.54 ; 700,284.54 700,305 745,305 745,220 664,220 664,243 666,245 682.28,245 700,262.72 700,284.54
  Bottom Layer w20: v1(1034,1104) 1034,929.36 1000,895.36 1000,834.64 1014.64,820 1050.91,820 1250.18,620.74 TP9.1@1250.18,499.88
\TB_STAT: D6.2 R10.2 R41.1 TP11.1 U1.16 | length 2755.7
  Top Layer w7.87: 1162,1213.57 U1.16@1133.74,1213.57 1171,1213.57 ; 1188.43,1213.57 v1@1282,1120 ; v1@1282,1131 1199.43,1213.57 1171,1213.57 ; 1292,1099 1177.43,1213.57 1171,1213.57
  Top Layer w10: 965,184 D6.2@984.53,184 ; 965,188 967,190 ; 1255.97,1149.99 1330.01,1149.99 R10.2@1330.01,1121 ; 1255.98,1150 1350,1150 1350,1100 1294,1100 1285,1109 v1@1285,1120 ; 965,165 965,245 1005,245 1005,165 965,165
  MidLayer2 w20: v1(985,233) 1122,370 1420.29,370 TP11.1@1550.18,499.88 1440,610.06 1440,965 v1@1285,1120
  Bottom Layer w10: 1275,1105 1275,1155 1349,1155 1350,1154 1350,1105 1275,1105
  other v1: 1286,1124
ACDET: C14.1 R3.1 R4.2 TP4.1 U1.6 | length 2519.4
  Top Layer w7.87: R3.1@792,1053 950.18,1211.18 ; 855,1136 932.57,1213.57 U1.6@976.26,1213.57
  Top Layer w10: TP4.1@500.18,506.18 TP4.1@500.18,499.88 ; TP4.1@523,499.88 527.88,495 547,495 617,565 688,565 725,602 725,721 ; TP4.1@527.88,499.88 TP4.1@500.18,499.88 ; 715,721 715,730 ; 715,926 725,916 ; 725,697 725,721 ; 760,1032 760,1043 ; R4.2@780.62,1191.63 780.62,1219.62 ; 797,1219.62 797,1034 725,962 725,721 ; 843,1123 845,1125 845,1185 ; 894,1175 855,1175 845,1185 ; TP4.1@500.18,499.88 505.29,505 543,505 613,575 683,575 715,607 715,730 ; 715,730 715,978 760,1023 760,1043 ; 760,1043 760,1220 780.24,1220 780.62,1219.62 ; 780.62,1219.62 844.62,1219.62 845,1219.24 845,1185
ACDRV: R12.1 TP3.1 U1.4 | length 1576.4
  Top Layer w7.87: 837.06,1245.06 U1.4@976.26,1245.06
  Top Layer w10: R12.1@780,1261.06 780,1290 ; 895,1246.25 883.19,1246.25 876.94,1240 761,1240 761,1290 780,1290 ; 905,1247 862,1290 780,1290
  Bottom Layer w20: TP3.1@350.18,499.88 350.18,508.18 412,570 577,570 720,713 720,1164 820,1264 v1(824.5,1264)
ACN: R16.1 U1.1 | length 752
  Top Layer w7.87: U1.1@964,1292.31 U1.1@976.26,1292.31
  Top Layer w10: R16.1@780,1471.06 780,1495 791,1495 ; 901,1373 U1.1@980.5,1293.5 ; U1.1@964,1293.5 900,1357.5 ; 791,1495 760,1495 760,1450 844,1450 895,1399 ; 791,1495 856,1495 900,1451 900,1398 ; 895,1399 896,1398 900,1398 ; 895,1399 895,1362.5 900,1357.5 ; 900,1357.5 900,1398
  other v1: 824.5,1474
ACOK: Q8.1 R11.1 TP5.1 U1.5 | length 2025.5
  Top Layer w7.87: U1.5@976.26,1229.32 928,1229.32 ; 928,1229.32 894.32,1229.32 885,1220 864,1220 864,1194 876.02,1194.02 882.03,1194.03 917.32,1229.32 928,1229.32
  Bottom Layer w10: 549,356 545,360 532,360 ; R11.1@589,312.5 615,338.5 ; 685,620 685,529 ; 532,360 605,433 605,535 610,535 685,535 685,529 ; 532,360 472,360 465,353 465,340 552,340 570,322 570,290 615,290 615,338.5 ; 615,338.5 615,385 685,455 685,529
  Bottom Layer w20: 610,524 610,535 610,547 760,697 760,1149 817,1206 v1(876,1206)
ACP: R15.1 U1.2 | length 654.4
  Top Layer w7.87: 943,1276.56 956,1276.56 ; 945.44,1276.56 956,1276.56 ; U1.2@976.26,1276.56 956,1276.56
  Top Layer w10: R15.1@780.35,1401.06 780.35,1429.35 781,1430 796,1430 ; 835,1375 828,1375 ; 943,1277.75 940.25,1277.75 865,1353 865,1365 855,1375 828,1375 ; 950,1278 875,1353 875,1389 834,1430 796,1430 ; 796,1430 760,1430 760,1375 828,1375
  other v1: 824,1404
BAT: C6.1 C7.1 C8.1 C9.1 C28.2 C30.1 D8.1 J2.1 JP1.1 JP6.2 R23.2 R27.2 | length 6686.9
  Top Layer w10: C28.2@1496,1325 1526,1325 1666,1465 1757,1465 1765,1457 R23.2@1765,1445 ; C28.2@1498.5,1337.5 1498.5,1360.5 ; 1524,1357 1525,1356 1525,1235 1475,1235 1475,1286 1456.01,1304.99 1371,1304.99 1370.5,1305.5 1370.5,1360.5 1539.5,1360.5 1649,1470 1780,1470 1780,1445 R23.2@1774,1439 ; 1680,1445 1675,1440 1675,1235 1686,1235 ; 1765,1470 1774,1461 R23.2@1774,1419.91 ; 1865,1445 1895,1475 2205,1475 ; 2151,1273 2255,1169 2255,1115 2345,1115 2345,1215 2260,1215 2245,1230 2245,1261 ; 2245,1235 1686,1235 ; 2245,1236 2245,1261 ; 2395,1368 2395,1565 2385,1565 ; 1686,1235 1545,1235 1545,1312 1678,1445 2113,1445 2233,1565 2385,1565 ; 2245,1261 2245,1309 2261,1325 2455,1325 2455,1565 2385,1565
  MidLayer1 w32: v1(1940,1363) v1(1990,1363) v1(2040,1363) v1(2090,1363) 2139,1363 v1(2140,1362)
  Bottom Layer w10: 2028,1475.11 2028,1428.67 2036,1420.67 ; 1905,1315 2375,1315 2375,1343.28 2386.72,1355 2455,1355 2455,1535 2293.28,1535 2233.39,1475.11 1905,1475.11 1905,1315
BATDRV: R28.2 TP13.1 U1.18 | length 1590.7
  Top Layer w7.87: U1.18@1133.74,1245.06 1223.06,1245.06 ; 1326,1286 1264,1286 1223.06,1245.06 ; 1350,1245.06 1223.06,1245.06
  Top Layer w10: 1264.78,1285 1350,1285 1350,1247
  MidLayer2 w20: v1(1285,1260) 1330,1215 1330,1130 1480,980 1480,636 1546,570 1780.06,570 TP13.1@1850.18,499.88
BATSRC: R29.1 U1.17 | length 601.8
  Top Layer w7.87: U1.17@1133.74,1229.32 1166.68,1229.32 1190,1229.32 ; 1254,1191 1253,1191 1214.68,1229.32 1190,1229.32 ; 1344,1225.13 1343.13,1226 1229,1226 1225.68,1229.32 1190,1229.32
  Top Layer w10: 1220,1225 1275,1170 1300,1170 ; 1289,1207 1289,1170 1300,1170 ; R29.1@1330.01,1191 1330.01,1225.13 1349.87,1225.13 1350,1225 1350,1170 1300,1170
  other v1: 1285,1190
BTST: pad.0@1010,1464 R19.1 U1.25 | length 563.8
  Top Layer w7.87: U1.25@1055,1323.8 1055,1453
  Top Layer w10: pad.0@1025,1445 pad.0@1008,1445 ; 1036.84,1445 1055,1426.84 1055,1426.78 1056.39,1425.39 ; 1056.11,1420.89 1085,1449.78 1085,1492 ; R19.1@1061,1486.01 1061,1505 R19.1@1055,1505 ; pad.0@1008,1445 1054,1445 1085,1476 1085,1492 ; pad.0@1008,1445 995,1445 995,1505 R19.1@1055,1505 ; R19.1@1055,1505 1085,1505 1085,1492
CMPIN: J3.5 JP3.1 R45.1 U1.13 | length 4336.7
  Top Layer w7.87: 1086.5,1144.5 1120,1111 1114,1111 1086.5,1138.5 U1.13@1086.5,1166.32 1086.5,1148 ; R45.1@1257.5,920 R45.1@1271,906.5
  Top Layer w10: R45.1@1271,906.5 1271,930 ; 1325,871 1325,885 ; 1455,467 1455,477 ; 1455,728 1455,477 ; 1465,459 1465,455 1701.18,218.82 J3.5@1701.18,150 ; 1465,502 1465,509 ; 1465,718 1298,885 ; J3.5@1685,166.18 J3.5@1695,156.18 ; 1271,930 1245,930 1245,885 1298,885 ; 1271,930 1320,930 1325,925 1325,885 ; 1298,885 1311,885 ; 1311,885 1325,885 ; 1311,885 1465,731 1465,509 ; 1455,477 1455,459 1695,219 J3.5@1695,156.18 ; 1465,509 1465,464.72 1715,214.72 1715,163.82 J3.5@1701.18,150 ; J3.5@1695,156.18 J3.5@1701.18,150
  MidLayer2 w20: v1(1120,1104) 1120,1095 v1(1310,905) ; J3.5@1701.18,150 1774.18,77 1950,77 2240,367 2240,618 2250,628 2250,763 ; JP3.1@2300,910 2250.47,860.47 ; 2250,763 2250.47,763.47 2250.47,860.47 ; 2250,763 2250,860 2250.47,860.47
CMPOUT: J3.6 JP4.2 R37.1 R45.2 U1.14 | length 5474.6
  Top Layer w7.87: U1.14@1102.24,1151 U1.14@1102.24,1166.32
  Top Layer w10: U1.14@1105.43,1152.35 1122.65,1152.35 1185,1090 1185,1013 ; 1106.76,1165 1154,1165 1159.5,1159.5 ; 1108.5,1159.5 1159.5,1159.5 ; R37.1@1201,969.99 1187.01,969.99 1185,972 1185,1013 ; R45.2@1271,969.5 R45.2@1285.5,955 ; 1322,965 1295,992 1295,997 ; 1350,950 1295,950 ; 1355,885 1355,965 1295,965 ; 1485.09,472.91 1485.09,739.19 ; 1485.09,477.91 1800.5,162.5 1800.5,157.5 1485.64,472.36 ; 1495.18,729.11 1345,879.28 1345,887 ; 1777,195 J3.6@1839,195 ; J3.6@1835,153.98 J3.6@1838.98,150 ; J3.6@1845,156.02 J3.6@1838.98,150 ; 1159.5,1159.5 1265,1054 1265,1016.72 1276.72,1005 1295,1005 1295,997 ; 1185,1013 1185,950 1295,950 ; 1295,950 1295,965 ; 1295,950 1328.28,950 1345,933.28 1345,909 ; 1295,965 1295,997 ; 1345,887 1345,909 ; 1345,887 1485.64,746.36 1485.64,472.36 ; 1345,909 1345,895 1495.18,744.82 1495.18,477.1 1776.78,195.5 1777.5,195.5 J3.6@1823,150 ; 1485.64,472.36 1808,150 J3.6@1823,150 ; J3.6@1823,150 J3.6@1838.98,150
  MidLayer2 w20: J3.6@1838.98,150 1972,150 2210,388 2210,589.96 2150.47,649.49 2150.47,692.47 2200,742 JP4.2@2200,790 JP4.2@2191,790
CMSRC: R13.1 R14.1 TP2.1 U1.3 | length 2063.8
  Top Layer w7.87: 852,1310 867.81,1310 917,1260.81 U1.3@976.26,1260.81
  Top Layer w10: R13.1@780,1331.06 780,1355 ; 867.81,1310 859,1310 852,1310 813,1310 760,1310 760,1355 780,1355 ; 925,1262.43 845,1342.43 845,1355 780,1355
  Bottom Layer w10: TP2.1@200.18,499.88 188,512.06 188,615 233,615 ; R14.1@210.5,600 218,607.5 225.5,607.5 233,615 ; 332,615 233,615
  Bottom Layer w20: TP2.1@200.18,499.88 310.29,610 559,610 680,731 680,1180 825.5,1325.5 v1(825.5,1334)
GND: C14.2 C17.2 C18.2 C19.2 C22.1 C29.2 C30.2 C31.2 C32.2 C33.2 C34.1 C35.1 C37.2 J3.1 NT1.1 Q8.2 R4.1 R9.2 R14.2 R20.2 R32.2 R34.1 R36.1 R47.2 TP15.1 TP16.1 U1.22 U2.2 | length 30398.3
  Top Layer w7.87: U1.22@1102.24,1335.24 U1.22@1102.24,1323.8 ; U1.22@1103,1312 1106,1312 1106,1333 1117,1344 1140,1344 v1(1150,1354) ; U1.22@1102.24,1323.8 1102.24,1342.24 1116,1356 1148,1356 v1(1150,1354) ; U1.22@1102.24,1323.8 1102.24,1336.24 1120,1354 v1(1150,1354)
  Top Layer w10: 145,535 45,535 45,465 144,465 144,400 ; v1(200,400) 144,400 ; 365.53,175 ccw(c175.53,175) 365,189.12 ; 440,365 331,365 365,331 365,189.12 ; v1(570,1630) 550,1630 550,1699.46 ; R4.1@717.63,1191.63 717.63,1219.63 718,1220 740,1220 ; C31.2@801,906.5 801,929 806,929 ; 855.18,410.82 855.18,522.67 822.96,554.88 795.12,554.88 775,575 775,920.72 783.28,929 806,929 ; 874,498 927.12,444.88 972.96,444.88 1005.18,477.1 1005.18,522.67 972.96,554.88 953.4,554.88 945,563.28 945,930 ; 895,467 895,929 806,929 ; R47.2@961,906.5 953.5,906.5 945,915 945,930 ; v1(1040,700) 1040,825 1055,825 ; 1045.18,400.18 1045.18,526.6 975,596.78 975,929.72 974.72,930 945,930 ; v1@1105,701 1106,700 v1(1120,700) ; v1(1150,1354) 1150,1405 1285,1405 1285,1401.78 1238.22,1355 1175,1355 1164,1344 1117,1344 1127,1354 1130,1354 1145,1369 1145,1405.06 1160.59,1405.06 1160.65,1405 ; 1245,704 1296,704 v1(1300,700) ; 1379,969 1379,1010 ; 1415,1079 1415,1070 ; 1475.5,1196.5 1475,1197 1475,1215 2180.72,1215 2195,1200.72 ; C30.2@1498.5,1196.5 1475,1196.5 1475,1170.5 ; C29.2@1498.5,1532.5 1476,1532.5 ; 1507.28,1135 1485,1135 ; 1508,1070 1500.72,1070 ; 1519,1215 1519.5,1214.5 1519.5,1205 ; 1530,738.28 1500.14,768.14 ; 1545,1202 1545,1156 1534,1145 1485,1145 ; 1589,1205 1519.5,1205 ; 1605.18,440.18 1605.18,522.67 1572.84,555 1515.18,555 1515.18,753.11 1500.14,768.14 ; 1645.18,438.18 1645.18,522.67 1660.25,537.75 ; 1654.25,531.75 1660.25,537.75 ; 1675,552.49 1660.25,537.75 ; 2135,175 cw(c2325,175) 2325,365 ; 2365,1189 2365,1255 2455,1255 2455,365 2227,365 2135,273 2135,35 365,35 365,189.12 ; 144,400 144,365 175.53,365 cw(c175.53,175) 365,189.12 ; 550,1699.46 550,1530 557.72,1530 585,1557.28 585,1699 584.54,1699.46 550,1699.46 ; 740,1220 740,1095 677.28,1095 565,1207.28 565,1289 625,1289 625,1244.72 649.72,1220 740,1220 ; 1055,825 1055,619.72 1115,559.72 1115,554.88 1094.58,554.88 1025,624.46 1025,825 1055,825 ; 1370,1033 1370,1074 ; 1370,1033 1370,982 1375,977 1375,893.28 1500.14,768.14 ; 1370,1033 1371,1032 1379,1032 ; 1370,1074 1370,1080 1393,1080 ; 1370,1074 1374,1070 1393,1070 ; 1379,1010 1440,1010 1440,1070 ; 1379,1010 1379,1032 ; 1379,1032 1415,1032 1415,1051 ; 1379,1032 1379,1035 1393,1049 R9.2@1392.99,1051 ; R9.2@1392.99,1051 1393,1070 ; R9.2@1392.99,1051 1415,1051 ; 1393,1070 1393,1080 ; 1393,1070 1415,1070 ; 1393,1080 1463.28,1080 ; 1415,1051 1415,1070 ; 1415,1070 1440,1070 ; 1440,1070 1500.72,1070 ; 1463.28,1080 1490.72,1080 1500.72,1070 ; 1463.28,1080 1475,1091.72 1475,1145 ; 1475,1145 1475,1170.5 ; 1475,1145 1475,1138.28 1478.28,1135 1485,1135 ; 1475,1170.5 1485,1170.5 ; 1476,1532.5 1476,1541.31 1485,1550.31 1485,1565 1594.72,1565 1615,1544.72 1615,1515 1565,1465 1545,1465 1545,1497.28 1532.28,1510 1476,1510 1476,1532.5 ; 1485,1135 1485,1145 ; 1485,1145 1485,1170.5 ; 1485,1170.5 1519.5,1170.5 1519.5,1205 ; 655,1596 666,1585 748.28,1585 760,1573.28 760,1515 805,1515 805,1566.72 734.72,1637 655,1637 655,1596 ; 1105,640.28 1105,825 1135,825 1135,615 1130.28,615 1105,640.28 ; 1245,654.28 1245,865 1289.72,865 1435,719.72 1435,555 1344.28,555 1245,654.28
  Top Layer w20: 1077,150 J3.1@1150,150 ; 1150,63 J3.1@1150,150 ; 1150,222 J3.1@1150,150 ; 1213,150 J3.1@1150,150
  Bottom Layer w10: 107,635 172,635 ; R14.2@147.5,602.79 168,623.28 ; 175.53,365 cw(c175.53,175) 365.53,175 ; 195.12,424 216,444.88 ; v1(200,400) 185,385 185,365 ; 239.12,444.88 222.96,444.88 ; 444,215 446.72,215 ; 460.4,215 446.72,215 ; Q8.2@516,266.79 Q8.2@506.72,266.79 ; 1145,1384 1145,1435 1330,1435 1330,1370 1190,1370 1155,1335 1125,1335 1125,1345.72 1145,1365.72 1145,1393 C22.1@1238,1393 ; C37.2@1589.98,249.77 1570.23,249.77 1570,249.53 ; C35.1@1779.5,791 1779.5,818 1805,843.5 ; 1781,964.28 1955,1138.28 1955,1143.28 ; 1805,988.28 1805,603.64 1756.25,554.88 1680.53,554.88 1475,760.42 1475,1225 1637.28,1225 1867.28,1455 1885,1455 1885,1306.72 1896.72,1295 2155,1295 2155,1178.28 2148.86,1172.14 ; 1816.72,1000 1883.28,1000 1895,988.28 1895,929 ; U2.2@1895,890.16 1895,907.83 ; 1895.3,907.53 1895,907.83 ; 1895.88,908.12 1902.76,915 1918.72,915 1955,951.28 1955,958 ; R32.2@1901,959 R32.2@1910.5,959 ; 1965,85 1645,85 1645,45 2135,45 2135,290 2210.12,365.12 2454.88,365.12 2454.88,1204.88 2351,1204.88 ; R34.1@1999,887.2 1999,909 ; 2135,175 cw(c2325,175) 2325,365 ; 2155,1250 2180,1225 2255,1225 2255,1216.72 2266.72,1205 2350.88,1205 2351,1204.88 ; 2171.72,1195 2148.86,1172.14 ; 2239,543 2281.28,543 ; 2333.14,594.86 2281.28,543 ; 2344.53,1065.74 2335.27,1075 2275,1075 2275,1105 2335.27,1105 2344.53,1114.26 ; 2344.53,1185.74 2335.27,1195 2006.72,1195 1955,1143.28 ; 2358.53,954.53 2275,954.53 2275,985 2345.12,985 ; 2365,845 2275,845 2275,865 2345.12,865 ; 168,623.28 168,631 172,635 ; 168,623.28 168,545.49 145.18,522.67 145.18,477.1 177.39,444.88 216,444.88 ; 168,623.28 179.72,635 ; 172,635 179.72,635 ; 179.72,635 548.64,635 655,741.36 655,765 45,765 45,445 95,445 95,365 185,365 ; 185,365 342,365 365,342 365,45 500,45 500,110 446.72,110 435,121.72 435,203.28 446.72,215 ; 216,444.88 222.96,444.88 ; 222.96,444.88 255.18,477.1 255.18,519.18 321,585 386,585 386,579.36 361.53,554.88 327.39,554.88 295.18,522.67 295.18,477.1 327.39,444.88 372.96,444.88 405.18,477.1 405.18,527.82 422.36,545 455,545 455,532.49 445.18,522.67 445.18,477.1 477.39,444.88 522.96,444.88 555.18,477.1 555.18,522.67 545,532.84 545,545 583,545 584,544 584,440.28 523.72,380 463.72,380 445,361.28 445,340 390.72,340 379,328.28 379,292.53 391.13,280.41 492.59,280.41 Q8.2@499.4,273.6 506.21,266.79 Q8.2@506.72,266.79 ; 446.72,215 495,215 495,255.07 Q8.2@506.72,266.79 ; 1570,249.53 1570,270 1625,270 1625,225 1570.28,225 1570,225.28 1570,249.53 ; 1895,907.83 1895,929 ; 1895,929 1895,955 1899,959 R32.2@1910.5,959 ; R32.2@1910.5,959 1954,959 1955,958 ; 1955,958 1955,1143.28 ; 1955,1143.28 1966.72,1155 2131.72,1155 2148.86,1172.14 ; 2281.28,543 2345.12,606.83 2345.12,865 ; 2345.12,865 2345.12,985 ; 2345.12,985 2345.12,1204.88 2351,1204.88 ; C34.1@1975,755 1979.28,755 2009.28,725 2225,725 2225,745 2180,745 2155.47,769.53 2155.47,808.44 2182.03,835 2225,835 2225,865 2164.72,865 2120.72,909 1988,909 1975,896 C34.1@1975,755
  other v1: 1310,330 425,391 2064,820 882,860 962,860 640,1195 1545,1530 683,1625
HIDRV: C23.1 pad.0@1160,1880 Q4.4 U1.26 | length 1290.6
  Top Layer w7.87: v1@1016,1411 v1@1016,1406 ; v1(1024,1414) 1039.25,1398.75 ; v1@1032,1423 1039.25,1415.75 1039.25,1398.75 ; U1.26@1039.25,1323.8 1039.25,1362 ; v1@1016,1406 1016,1397 1039.25,1373.75 1039.25,1362 ; v1@1016,1406 1039.25,1382.75 1039.25,1362 ; 1039.25,1362 1039.25,1398.75
  Top Layer w10: Q4.4@1082.64,1865 1082.64,1893.64 1084,1895 1145,1895 pad.0@1160,1880 1145,1865 Q4.4@1082.64,1865
  MidLayer1 w20: v1(1024,1414) 1034,1414 1060,1440 1060,1556 1090,1586 1090,1810 pad.0@1160,1880
  Bottom Layer w10: 1070,1855 1185,1855 1185,1905 1070,1905 1070,1855
IADP: C31.1 TP6.1 U1.7 | length 2003.1
  Top Layer w7.87: U1.7@964,1197.82 U1.7@976.26,1197.82
  Top Layer w10: 745,575 TP6.1@800.18,519.82 ; 772.14,973.86 745,946.72 745,586 745,555.06 TP6.1@800.18,499.88 ; 780.5,950.5 780.5,969.5 ; 792.27,993.98 755,956.72 755,922 ; TP6.1@800.18,513.18 TP6.1@800.18,499.88 ; C31.1@801,969.5 780.5,969.5 ; 815,1000 815,949 804,949 ; 815.64,1017.36 805.14,1006.86 ; 818,1019.72 818,1047 U1.7@965.63,1194.63 ; 847.64,1049.36 845,1046.72 845,949 804,949 ; 975,1193 975,1176.72 805.14,1006.86 ; 755,922 755,565 TP6.1@800.18,519.82 ; 755,922 755,929 775,949 804,949 ; 780.5,969.5 780.5,982.21 805.14,1006.86 ; TP6.1@800.18,499.88 TP6.1@800.18,519.82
